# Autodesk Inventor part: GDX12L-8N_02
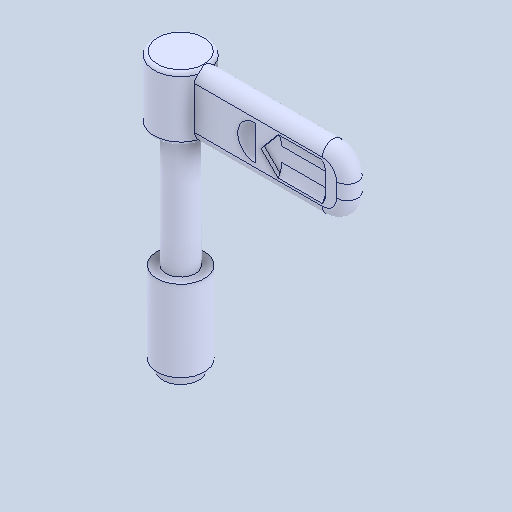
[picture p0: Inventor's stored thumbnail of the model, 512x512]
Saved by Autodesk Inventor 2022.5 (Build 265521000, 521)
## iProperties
Created: 2024-06
Part Number: GDX12L-8N_02
Material: 一般
Document SubType Name: Modeling
Designer: ImaoCorp
Density: 1 g/cm^3
Appearance: 既定
Author: ImaoCorp
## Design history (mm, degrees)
feature "GDX12L-8N_02"
node "ソリッド1"
